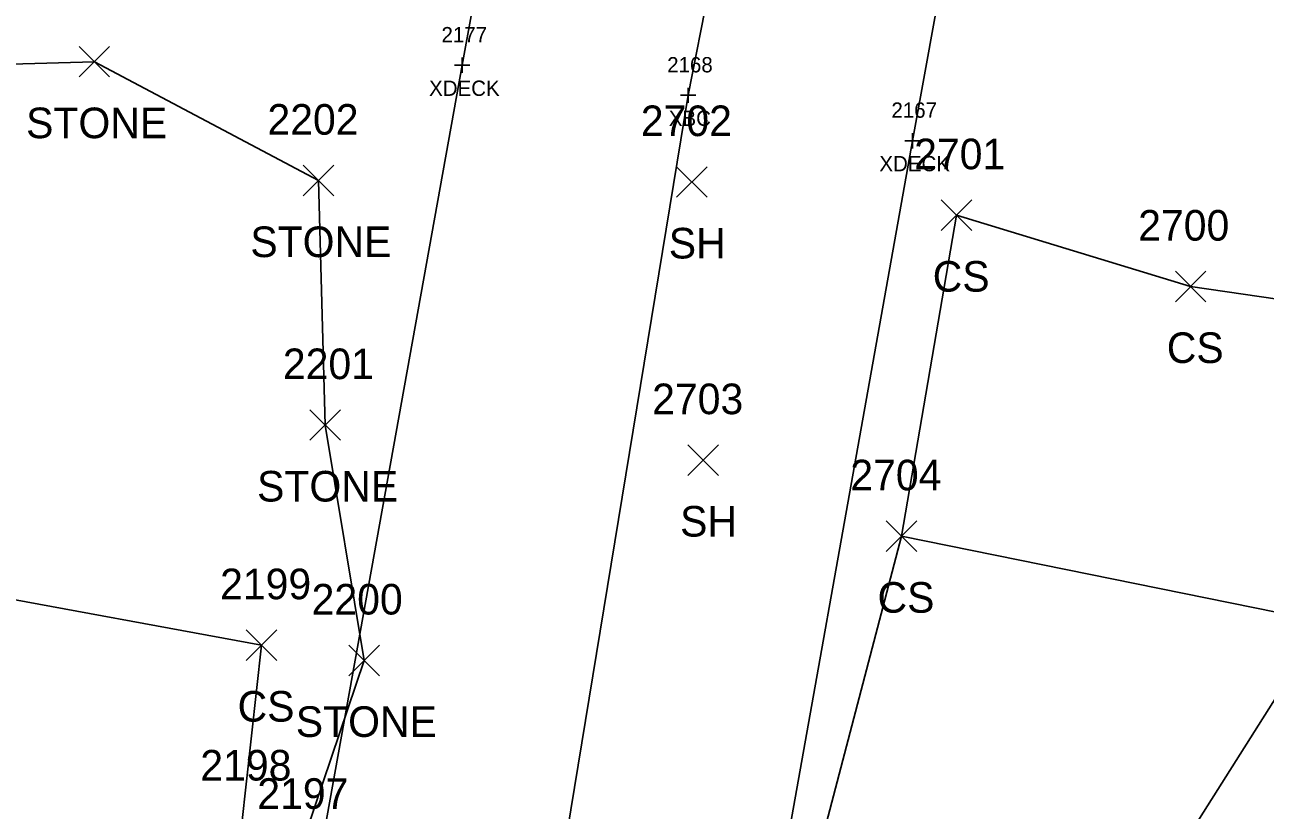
# Model space of a CAD drawing. Extents: x 1472022 to 1479249, y 777216 to 786527.
# Drawn here: x 1473615.2 to 1473696.2, y 779345 to 779396.3 of the extents above; entities that cross this region are included whole.
import ezdxf

# ---------------------------------------------------------------- set-up
doc = ezdxf.new("R2010")
doc.units = 0
for name, color, linetype in [('B_A', 7, 'Continuous'), ('B_I', 7, 'Continuous'), ('B_TIC', 7, 'Continuous'), ('BELB', 7, 'Continuous'), ('L_A', 7, 'Continuous'), ('L_I', 7, 'Continuous'), ('L_TIC', 7, 'Continuous'), ('LABL', 7, 'Continuous'), ('LASF', 7, 'Continuous'), ('LELB', 7, 'Continuous')]:
    doc.layers.add(name, color=color, linetype=linetype)

msp = doc.modelspace()

# ---------------------------------------------------------------- linework, layer by layer
at = {"layer": 'B_TIC'}
for p, q in [((1473643.773, 779393.665), (1473643.849, 779393.665)), ((1473658.536, 779391.701), (1473658.612, 779391.701)), ((1473673.182, 779388.735), (1473673.258, 779388.735))]:
    msp.add_line(p, q, dxfattribs=at)
for points in [[(1473643.27, 779393.665), (1473644.27, 779393.665)], [(1473643.77, 779393.165), (1473643.77, 779394.165)], [(1473658.533, 779391.201), (1473658.533, 779392.201)], [(1473658.033, 779391.701), (1473659.033, 779391.701)], [(1473672.679, 779388.735), (1473673.679, 779388.735)], [(1473673.179, 779388.235), (1473673.179, 779389.235)]]:
    msp.add_lwpolyline(points, dxfattribs=at)
at = {"layer": 'BELB'}
for points in [[(1473632.636, 779331.636), (1473643.77, 779393.665), (1473661.765, 779492.346), (1473674.974, 779565.301), (1473690.2, 779649.783), (1473708.219, 779748.211)], [(1473648.225, 779328.947), (1473658.533, 779391.701), (1473677.734, 779489.348), (1473690.328, 779561.525), (1473706.168, 779646.866), (1473724.089, 779745.087)], [(1473662.069, 779326.366), (1473673.179, 779388.735), (1473691.037, 779487.093), (1473704.302, 779559.921), (1473719.463, 779644.729), (1473737.376, 779742.924)]]:
    msp.add_lwpolyline(points, dxfattribs=at)
at = {"layer": 'L_TIC'}
for points in [[(1473618.749, 779392.899), (1473620.749, 779394.899)], [(1473620.749, 779392.899), (1473618.749, 779394.899)], [(1473633.394, 779385.127), (1473635.394, 779387.127)], [(1473635.394, 779385.127), (1473633.394, 779387.127)], [(1473657.779, 779385.036), (1473659.779, 779387.036)], [(1473659.779, 779385.036), (1473657.779, 779387.036)], [(1473675.064, 779382.868), (1473677.064, 779384.868)], [(1473677.064, 779382.868), (1473675.064, 779384.868)], [(1473690.351, 779378.203), (1473692.351, 779380.203)], [(1473692.351, 779378.203), (1473690.351, 779380.203)], [(1473633.834, 779369.149), (1473635.834, 779371.149)], [(1473635.834, 779369.149), (1473633.834, 779371.149)], [(1473658.519, 779366.858), (1473660.519, 779368.858)], [(1473660.519, 779366.858), (1473658.519, 779368.858)], [(1473671.461, 779361.88), (1473673.461, 779363.88)], [(1473673.461, 779361.88), (1473671.461, 779363.88)], [(1473671.461, 779361.88), (1473673.461, 779363.88)], [(1473673.461, 779361.88), (1473671.461, 779363.88)], [(1473629.664, 779354.761), (1473631.664, 779356.761)], [(1473631.664, 779354.761), (1473629.664, 779356.761)], [(1473636.365, 779353.762), (1473638.365, 779355.762)], [(1473638.365, 779353.762), (1473636.365, 779355.762)]]:
    msp.add_lwpolyline(points, dxfattribs=at)
at = {"layer": 'LABL'}
msp.add_lwpolyline([(1473734.761, 779391.164), (1473723.282, 779369.856), (1473700.056, 779357.278), (1473685.537, 779334.297), (1473674.134, 779323.101), (1473682.283, 779304.265)], dxfattribs=at)
at = {"layer": 'LASF'}
msp.add_lwpolyline([(1473633.087, 779342.06), (1473637.365, 779354.762), (1473634.834, 779370.149), (1473634.394, 779386.127), (1473619.749, 779393.899), (1473604.914, 779393.472), (1473602.815, 779381.231), (1473597.403, 779362.46), (1473593.626, 779347.936), (1473579.62, 779350.93), (1473559.31, 779355.605), (1473561.077, 779365.729), (1473563.085, 779383.248), (1473565.836, 779398.856), (1473566.452, 779410.85), (1473556.368, 779410.02), (1473539.023, 779405.146), (1473523.923, 779401.839), (1473511.027, 779390.757), (1473502.061, 779373.783), (1473492.386, 779361.708)], dxfattribs=at)
at = {"layer": 'LELB'}
for points in [[(1473754.244, 779287.289), (1473757.417, 779300.327), (1473754.668, 779316.814), (1473753.602, 779330.821), (1473747.512, 779344.855), (1473732.484, 779357.395), (1473723.282, 779369.856), (1473709.742, 779376.521), (1473691.351, 779379.203), (1473676.064, 779383.868), (1473672.461, 779362.88), (1473665.859, 779337.68), (1473665.543, 779331.053)], [(1473592.018, 779340.28), (1473611.872, 779337.57), (1473629.751, 779333.054), (1473629.364, 779343.911), (1473630.664, 779355.761), (1473611.728, 779359.237), (1473597.403, 779362.46), (1473580.816, 779362.299), (1473561.077, 779365.729)], [(1473672.461, 779362.88), (1473700.056, 779357.278), (1473719.448, 779340.632), (1473717.818, 779339.713), (1473720.79, 779321.083), (1473722.515, 779302.887), (1473718.197, 779289.069), (1473701.465, 779291.304), (1473704.01, 779316.114), (1473685.537, 779334.297), (1473672.995, 779339.334), (1473669.271, 779327.361), (1473669.965, 779320.226), (1473668.933, 779306.253), (1473668.649, 779306.084)]]:
    msp.add_lwpolyline(points, dxfattribs=at)

# ---------------------------------------------------------------- texts
at = {"layer": 'B_A'}
for s, p in [('XDECK', (1473641.613, 779391.665)), ('XBC', (1473657.269, 779389.701)), ('XDECK', (1473671.021, 779386.735))]:
    msp.add_text(s, height=1, dxfattribs=at).set_placement(p)
at = {"layer": 'B_I'}
for s, p in [('2177', (1473642.424, 779395.165)), ('2168', (1473657.163, 779393.201)), ('2167', (1473671.809, 779390.235))]:
    msp.add_text(s, height=1, dxfattribs=at).set_placement(p)
at = {"layer": 'L_A'}
for s, p in [('STONE', (1473615.293, 779388.899)), ('STONE', (1473629.937, 779381.127)), ('SH', (1473657.267, 779381.036)), ('CS', (1473674.505, 779378.868)), ('CS', (1473689.792, 779374.203)), ('STONE', (1473630.378, 779365.149)), ('SH', (1473658.007, 779362.858)), ('CS', (1473670.902, 779357.88)), ('CS', (1473670.902, 779357.88)), ('CS', (1473629.105, 779350.761)), ('STONE', (1473632.908, 779349.762))]:
    msp.add_text(s, height=2, dxfattribs=at).set_placement(p)
at = {"layer": 'L_I'}
for s, p in [('2202', (1473631.055, 779389.127)), ('2702', (1473655.44, 779389.036)), ('2701', (1473673.292, 779386.868)), ('2700', (1473687.925, 779382.203)), ('2201', (1473632.063, 779373.149)), ('2703', (1473656.18, 779370.858)), ('2704', (1473669.123, 779365.88)), ('2704', (1473669.123, 779365.88)), ('2199', (1473627.963, 779358.761)), ('2200', (1473633.94, 779357.762)), ('2198', (1473626.671, 779346.911)), ('2197', (1473630.394, 779345.06)), ('2197', (1473630.394, 779345.06)), ('2197', (1473630.394, 779345.06))]:
    msp.add_text(s, height=2, dxfattribs=at).set_placement(p)

doc.saveas('drawing.dxf')
